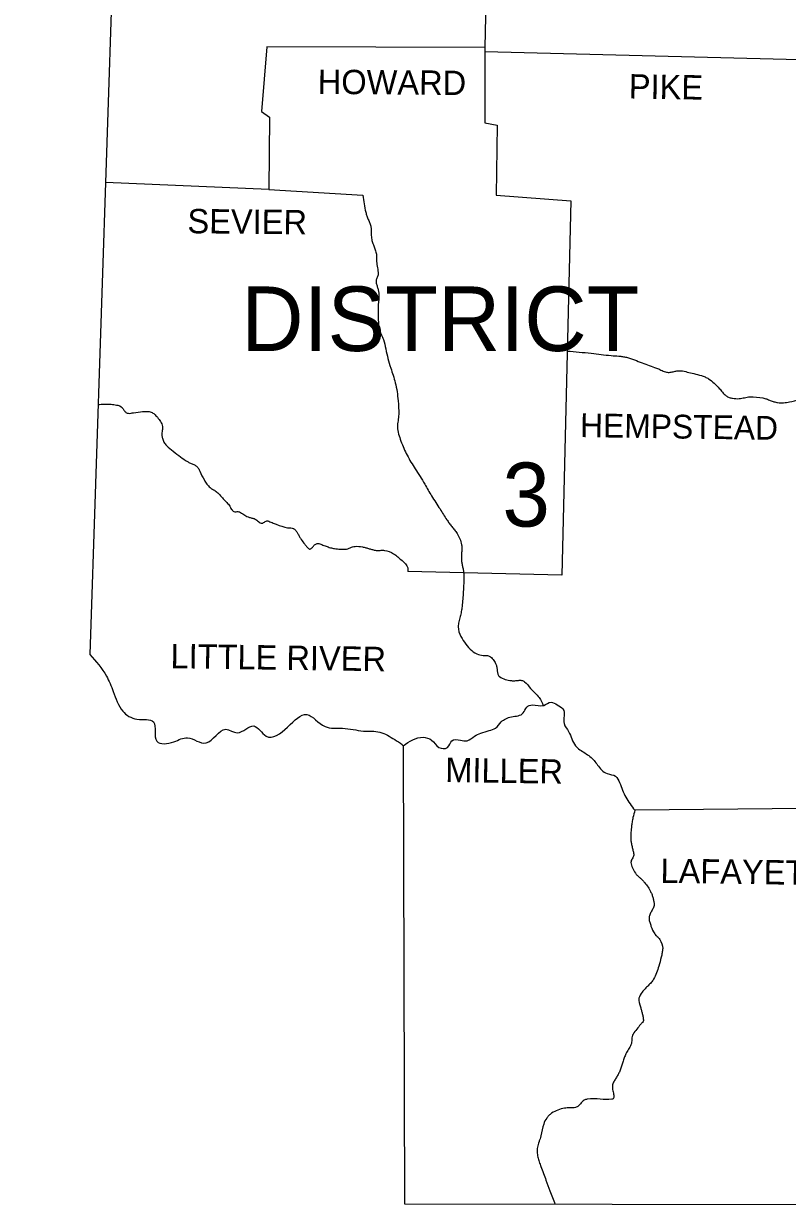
# Model space of a CAD drawing. Extents: x 1334737.7 to 1334827.2, y 402732.3 to 402753.5.
# Drawn here: x 1334761.977 to 1334763.502, y 402745.105 to 402747.469 of the extents above; entities that cross this region are included whole.
import ezdxf

# ---------------------------------------------------------------- set-up
doc = ezdxf.new("R2010")
doc.units = 0
doc.layers.add('Default', color=7, linetype='Continuous')

msp = doc.modelspace()

# ---------------------------------------------------------------- linework, layer by layer
at = {"layer": 'Default'}
for points in [[(1334761.9774, 402751.1577), (1334762.2116, 402749.2778), (1334762.1098, 402746.2091)], [(1334763.2289, 402748.5829), (1334763.2274, 402748.1195), (1334763.1708, 402748.1184), (1334763.1753, 402748.0845), (1334763.121, 402748.0856), (1334763.1199, 402748.0607), (1334763.0667, 402748.0607), (1334763.0679, 402748.0426), (1334762.9887, 402748.0404), (1334762.9875, 402747.9714), (1334762.9106, 402747.9781), (1334762.8982, 402747.4216), (1334762.4627, 402747.4228), (1334762.4525, 402747.2938), (1334762.4683, 402747.2825), (1334762.4672, 402747.1377), (1334762.1411, 402747.1521)], [(1334762.8982, 402747.4216), (1334762.8982, 402747.2712), (1334762.9231, 402747.2667), (1334762.9208, 402747.1264), (1334763.0701, 402747.1151), (1334763.052, 402746.3674), (1334762.7444, 402746.3753)], [(1334762.8982, 402747.4138), (1334763.5529, 402747.3966)], [(1334762.4672, 402747.1377), (1334762.655, 402747.1264)], [(1334762.7353, 402746.027), (1334762.7376, 402745.1119), (1334766.8832, 402745.1051)], [(1334763.5407, 402745.9014), (1334763.1979, 402745.898)]]:
    msp.add_lwpolyline(points, dxfattribs=at)
for points in [[(1334762.655, 402747.1264), (1334762.6606, 402747.0925), (1334762.6628, 402747.085), (1334762.6656, 402747.0777), (1334762.6686, 402747.0705), (1334762.6708, 402747.0631), (1334762.6715, 402747.0575), (1334762.6715, 402747.0518), (1334762.6715, 402747.0461), (1334762.672, 402747.0404), (1334762.6742, 402747.0319), (1334762.6773, 402747.0235), (1334762.6803, 402747.0151), (1334762.6821, 402747.0065), (1334762.6821, 402746.9941), (1334762.6828, 402746.9878), (1334762.6839, 402746.9816), (1334762.6849, 402746.9754), (1334762.6855, 402746.9692), (1334762.6849, 402746.9657), (1334762.6833, 402746.9624), (1334762.6817, 402746.959), (1334762.681, 402746.9556), (1334762.682, 402746.9489), (1334762.684, 402746.9421), (1334762.6859, 402746.9353), (1334762.6867, 402746.9285), (1334762.6855, 402746.9081), (1334762.6855, 402746.8911), (1334762.6867, 402746.8629), (1334762.6882, 402746.8564), (1334762.6908, 402746.8503), (1334762.6935, 402746.8442), (1334762.6957, 402746.838), (1334762.7048, 402746.8006), (1334762.7104, 402746.7814), (1334762.7195, 402746.752), (1334762.7251, 402746.7158), (1334762.7263, 402746.6887), (1334762.7259, 402746.6824), (1334762.725, 402746.6762), (1334762.7242, 402746.67), (1334762.724, 402746.6638), (1334762.7308, 402746.6355), (1334762.7432, 402746.6072), (1334762.7591, 402746.5801), (1334762.7783, 402746.5495), (1334762.7919, 402746.5258), (1334762.8088, 402746.4998), (1334762.8224, 402746.4783), (1334762.8272, 402746.4714), (1334762.8325, 402746.4647), (1334762.8377, 402746.4581), (1334762.8428, 402746.4511), (1334762.8518, 402746.4285), (1334762.8523, 402746.4206), (1334762.852, 402746.4126), (1334762.8516, 402746.4047), (1334762.8518, 402746.3968), (1334762.8529, 402746.3895), (1334762.8544, 402746.3822), (1334762.8557, 402746.3748), (1334762.8563, 402746.3674), (1334762.8552, 402746.3346), (1334762.8529, 402746.3052), (1334762.8513, 402746.2949), (1334762.8489, 402746.2848), (1334762.8465, 402746.2746), (1334762.845, 402746.2645), (1334762.8507, 402746.2453), (1334762.8722, 402746.217), (1334762.8857, 402746.2091), (1334762.8916, 402746.2077), (1334762.8977, 402746.2074), (1334762.9039, 402746.2069), (1334762.9095, 402746.2045), (1334762.9161, 402746.1973), (1334762.9208, 402746.1887), (1334762.9225, 402746.1827), (1334762.923, 402746.1763), (1334762.9241, 402746.1701), (1334762.9254, 402746.1673), (1334762.9276, 402746.165), (1334762.9391, 402746.1594), (1334762.9514, 402746.157), (1334762.9547, 402746.1567), (1334762.9581, 402746.1568), (1334762.9652, 402746.1576), (1334762.9718, 402746.1575), (1334762.9774, 402746.1548), (1334762.9898, 402746.1412), (1334763.0068, 402746.1231), (1334763.0151, 402746.1072)], [(1334763.0629, 402746.8153), (1334763.1108, 402746.8108), (1334763.1504, 402746.8063), (1334763.1658, 402746.8051), (1334763.1734, 402746.8043), (1334763.1772, 402746.8037), (1334763.181, 402746.8029), (1334763.1891, 402746.8005), (1334763.197, 402746.7977), (1334763.2126, 402746.7916), (1334763.2409, 402746.7814), (1334763.2455, 402746.7795), (1334763.2499, 402746.7774), (1334763.2544, 402746.7753), (1334763.259, 402746.7735), (1334763.2665, 402746.7727), (1334763.2742, 402746.774), (1334763.2819, 402746.7756), (1334763.2896, 402746.7758), (1334763.3026, 402746.7733), (1334763.3156, 402746.7701), (1334763.3307, 402746.7661), (1334763.338, 402746.7635), (1334763.3415, 402746.7619), (1334763.345, 402746.7599), (1334763.3563, 402746.7509), (1334763.3665, 402746.7407), (1334763.3697, 402746.7371), (1334763.3727, 402746.7332), (1334763.3801, 402746.726), (1334763.3864, 402746.7226), (1334763.3929, 402746.7209), (1334763.4061, 402746.7203), (1334763.4114, 402746.721), (1334763.4168, 402746.7221), (1334763.4222, 402746.7232), (1334763.4276, 402746.7237), (1334763.4536, 402746.7215), (1334763.461, 402746.7195), (1334763.4683, 402746.7167), (1334763.4756, 402746.7141), (1334763.483, 402746.7124), (1334763.4889, 402746.712), (1334763.4949, 402746.712), (1334763.5067, 402746.7135), (1334763.526, 402746.7181), (1334763.5486, 402746.7237), (1334763.5627, 402746.7259), (1334763.5698, 402746.7262), (1334763.5769, 402746.726), (1334763.5823, 402746.7252), (1334763.5876, 402746.7238), (1334763.593, 402746.7224), (1334763.5984, 402746.7215), (1334763.6125, 402746.7206), (1334763.6266, 402746.7203), (1334763.6349, 402746.721), (1334763.6431, 402746.7223), (1334763.6513, 402746.7235), (1334763.6554, 402746.7238), (1334763.6595, 402746.7237), (1334763.6678, 402746.7227), (1334763.6925, 402746.7155), (1334763.7085, 402746.7087), (1334763.7242, 402746.7016)], [(1334762.1263, 402746.7083), (1334762.1378, 402746.7094), (1334762.1494, 402746.7092), (1334762.1604, 402746.7078), (1334762.1697, 402746.7056), (1334762.1738, 402746.7024), (1334762.1776, 402746.6973), (1334762.1817, 402746.6927), (1334762.1867, 402746.6909), (1334762.1969, 402746.6921), (1334762.215, 402746.6943), (1334762.2192, 402746.6947), (1334762.2235, 402746.6947), (1334762.2277, 402746.6942), (1334762.2319, 402746.6932), (1334762.2356, 402746.6915), (1334762.2388, 402746.6891), (1334762.2416, 402746.6862), (1334762.2444, 402746.683), (1334762.2478, 402746.6787), (1334762.2508, 402746.6744), (1334762.2531, 402746.6698), (1334762.2546, 402746.6649), (1334762.2548, 402746.6607), (1334762.2542, 402746.6564), (1334762.2536, 402746.6522), (1334762.2534, 402746.6479), (1334762.2546, 402746.6412), (1334762.2559, 402746.6371), (1334762.2576, 402746.6332), (1334762.2625, 402746.6264), (1334762.2761, 402746.6151), (1334762.2908, 402746.6038), (1334762.3043, 402746.5948), (1334762.3073, 402746.593), (1334762.3105, 402746.5915), (1334762.3169, 402746.5886), (1334762.3228, 402746.5851), (1334762.327, 402746.5801), (1334762.3292, 402746.5755), (1334762.3383, 402746.5574), (1334762.3433, 402746.5497), (1334762.3463, 402746.5461), (1334762.3496, 402746.5427), (1334762.3528, 402746.5403), (1334762.3564, 402746.5382), (1334762.36, 402746.5362), (1334762.3632, 402746.5337), (1334762.3779, 402746.5179), (1334762.3846, 402746.5111), (1334762.3876, 402746.5073), (1334762.3901, 402746.5031), (1334762.3927, 402746.4989), (1334762.3942, 402746.497), (1334762.396, 402746.4952), (1334762.3988, 402746.4941), (1334762.402, 402746.4943), (1334762.4054, 402746.4946), (1334762.4084, 402746.4941), (1334762.4127, 402746.4917), (1334762.4168, 402746.4889), (1334762.421, 402746.4862), (1334762.4254, 402746.4839), (1334762.4284, 402746.4829), (1334762.4316, 402746.4822), (1334762.4348, 402746.4814), (1334762.4378, 402746.4805), (1334762.4413, 402746.4786), (1334762.4445, 402746.4759), (1334762.4478, 402746.4733), (1334762.4514, 402746.4715), (1334762.4548, 402746.4718), (1334762.4582, 402746.4738), (1334762.4616, 402746.4757), (1334762.465, 402746.476), (1334762.4692, 402746.4744), (1334762.4734, 402746.4726), (1334762.4777, 402746.4708), (1334762.4819, 402746.4692), (1334762.5045, 402746.4624), (1334762.5077, 402746.462), (1334762.5109, 402746.4619), (1334762.5156, 402746.461), (1334762.5163, 402746.4606), (1334762.517, 402746.4602), (1334762.5217, 402746.4555), (1334762.5252, 402746.45), (1334762.5282, 402746.4442), (1334762.5299, 402746.4414), (1334762.5317, 402746.4387), (1334762.5387, 402746.4293), (1334762.5424, 402746.4248), (1334762.5464, 402746.4206), (1334762.5484, 402746.4197), (1334762.5505, 402746.4203), (1334762.5549, 402746.4243), (1334762.5596, 402746.429), (1334762.5621, 402746.4305), (1334762.5645, 402746.4308), (1334762.5729, 402746.4286), (1334762.5813, 402746.4255), (1334762.5898, 402746.4225), (1334762.5984, 402746.4206), (1334762.6092, 402746.4195), (1334762.6199, 402746.4195), (1334762.6248, 402746.4205), (1334762.6295, 402746.4224), (1334762.6343, 402746.4242), (1334762.6392, 402746.4251), (1334762.6539, 402746.424), (1334762.6607, 402746.4224), (1334762.6674, 402746.4205), (1334762.6742, 402746.4187), (1334762.681, 402746.4172), (1334762.6852, 402746.4169), (1334762.6895, 402746.4172), (1334762.6937, 402746.4175), (1334762.698, 402746.4172), (1334762.7161, 402746.4104), (1334762.733, 402746.3968), (1334762.7444, 402746.3821), (1334762.7444, 402746.3753)], [(1334762.1098, 402746.2091), (1334762.1426, 402746.1661), (1334762.1562, 402746.1355), (1334762.1754, 402746.096), (1334762.2037, 402746.0801), (1334762.2365, 402746.0745), (1334762.2433, 402746.036), (1334762.2772, 402746.0349), (1334762.3043, 402746.0428), (1334762.3417, 402746.0326), (1334762.3813, 402746.0598), (1334762.4039, 402746.053), (1334762.4367, 402746.0665), (1334762.4616, 402746.0462), (1334762.5045, 402746.0643), (1334762.543, 402746.0892), (1334762.5792, 402746.0654), (1334762.6143, 402746.062), (1334762.6561, 402746.0564), (1334762.6889, 402746.0541), (1334762.7183, 402746.0394), (1334762.7331, 402746.0292), (1334762.7353, 402746.027)], [(1334762.7353, 402746.027), (1334762.7749, 402746.0439), (1334762.7919, 402746.0383), (1334762.8066, 402746.0236), (1334762.8235, 402746.0236), (1334762.8326, 402746.0371), (1334762.8495, 402746.0383), (1334762.8631, 402746.0371), (1334762.8778, 402746.0462), (1334762.8903, 402746.0518), (1334762.9072, 402746.0575), (1334762.9197, 402746.062), (1334762.931, 402746.0745), (1334762.9514, 402746.0846), (1334762.9751, 402746.0926), (1334762.9819, 402746.1039), (1334762.9932, 402746.1084), (1334763.0158, 402746.1073), (1334763.0305, 402746.114), (1334763.043, 402746.1084), (1334763.0543, 402746.1005), (1334763.0565, 402746.0711), (1334763.0656, 402746.0552), (1334763.0792, 402746.027), (1334763.0984, 402746.0122), (1334763.1165, 402745.9975), (1334763.1233, 402745.9885), (1334763.1425, 402745.9715), (1334763.1595, 402745.9659), (1334763.1674, 402745.9534), (1334763.1798, 402745.924), (1334763.1979, 402745.898)], [(1334763.1979, 402745.898), (1334763.194, 402745.8835), (1334763.1924, 402745.8742), (1334763.1912, 402745.8652), (1334763.19, 402745.8392), (1334763.1909, 402745.8315), (1334763.1927, 402745.8238), (1334763.1946, 402745.8161), (1334763.1957, 402745.8086), (1334763.1948, 402745.8049), (1334763.1927, 402745.8012), (1334763.1907, 402745.7976), (1334763.19, 402745.7939), (1334763.1911, 402745.7885), (1334763.193, 402745.7831), (1334763.1991, 402745.7725), (1334763.2032, 402745.7676), (1334763.2076, 402745.7636), (1334763.212, 402745.7598), (1334763.216, 402745.7555), (1334763.2226, 402745.7469), (1334763.2285, 402745.7374), (1334763.2315, 402745.7309), (1334763.2338, 402745.7244), (1334763.2354, 402745.7178), (1334763.2364, 402745.7114), (1334763.2351, 402745.704), (1334763.2313, 402745.6967), (1334763.2275, 402745.6893), (1334763.2262, 402745.682), (1334763.2277, 402745.6743), (1334763.2301, 402745.6666), (1334763.2375, 402745.6514), (1334763.2399, 402745.6483), (1334763.2427, 402745.6458), (1334763.2454, 402745.6432), (1334763.2477, 402745.6401), (1334763.2534, 402745.622), (1334763.2523, 402745.6133), (1334763.2505, 402745.6045), (1334763.2455, 402745.5869), (1334763.2353, 402745.5609), (1334763.2329, 402745.5573), (1334763.2303, 402745.5539), (1334763.2244, 402745.5477), (1334763.2183, 402745.5416), (1334763.2126, 402745.5349), (1334763.2059, 402745.5225), (1334763.2093, 402745.5055), (1334763.2109, 402745.4987), (1334763.2127, 402745.4919), (1334763.2142, 402745.4851), (1334763.2147, 402745.4817), (1334763.2148, 402745.48), (1334763.2149, 402745.4784), (1334763.2128, 402745.4742), (1334763.211, 402745.4723), (1334763.2093, 402745.4704), (1334763.2018, 402745.4609), (1334763.1945, 402745.4512), (1334763.1925, 402745.4462), (1334763.1918, 402745.4407), (1334763.1914, 402745.435), (1334763.19, 402745.4297), (1334763.1876, 402745.4252), (1334763.1849, 402745.4207), (1334763.1822, 402745.4163), (1334763.1798, 402745.4116), (1334763.1768, 402745.4035), (1334763.1741, 402745.3952), (1334763.1715, 402745.3869), (1334763.1685, 402745.3788), (1334763.1652, 402745.3719), (1334763.1614, 402745.3651), (1334763.1574, 402745.3584), (1334763.1538, 402745.3517), (1334763.1531, 402745.3431), (1334763.1549, 402745.333), (1334763.1556, 402745.3246), (1334763.1544, 402745.3221), (1334763.1516, 402745.3211), (1334763.1289, 402745.3211), (1334763.1029, 402745.3211), (1334763.0964, 402745.3188), (1334763.0909, 402745.3135), (1334763.0854, 402745.3078), (1334763.0792, 402745.3042), (1334763.0739, 402745.3035), (1334763.0685, 402745.3036), (1334763.063, 402745.3036), (1334763.0577, 402745.303), (1334763.0443, 402745.2994), (1334763.0317, 402745.2929), (1334763.0262, 402745.2883), (1334763.0218, 402745.2832), (1334763.0158, 402745.2714), (1334763.0102, 402745.2476), (1334763.0085, 402745.242), (1334763.0065, 402745.2363), (1334763.0034, 402745.225), (1334763.0028, 402745.2154), (1334763.0042, 402745.2056), (1334763.0069, 402745.1959), (1334763.0102, 402745.1865), (1334763.0204, 402745.1594), (1334763.0283, 402745.1379), (1334763.0384, 402745.1114)]]:
    msp.add_spline(points, degree=3, dxfattribs=at)

# ---------------------------------------------------------------- texts
for s, height, rotation, p in [('HOWARD', 0.04865, 359.5145, (1334762.5645, 402747.3289)), ('PIKE', 0.04863, 359.0452, (1334763.1855, 402747.3198)), ('SEVIER', 0.04865, 359.4271, (1334762.3043, 402747.0506)), ('HEMPSTEAD', 0.0475, 359.1885, (1334763.0882, 402746.6434)), ('LITTLE RIVER', 0.048646, 359.1697, (1334762.2704, 402746.1819)), ('MILLER', 0.04863, 359.132, (1334762.819, 402745.9546)), ('LAFAYETTE', 0.04863, 359.1839, (1334763.2488, 402745.7532))]:
    msp.add_text(s, height=height, rotation=rotation, dxfattribs=at).set_placement(p)
for s, height, p in [('DISTRICT', 0.12895, (1334762.4118, 402746.8153)), ('3', 0.1278, (1334762.9333, 402746.4647))]:
    msp.add_text(s, height=height, dxfattribs=at).set_placement(p)

doc.saveas('drawing.dxf')
